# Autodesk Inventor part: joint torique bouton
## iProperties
Created: 2001-11
Part Number: joint torique bouton
Material: Par défaut
Document SubType Name: Modélisation
Designer: User
Control State: 0
Master: False
Checked Out: False
Shininess: 20.0
Length Units: 11269
Angle Units: 11279
Time Units: 11290
Mass Units: 11283
Length Display Precision: 3
Angle Display Precision: 2
Density: 0.0
Volumn: 0.0
Area: 0.0
PropertySet Name: Model Information
Author: User
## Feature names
1. Révolution1 [Revolution]
